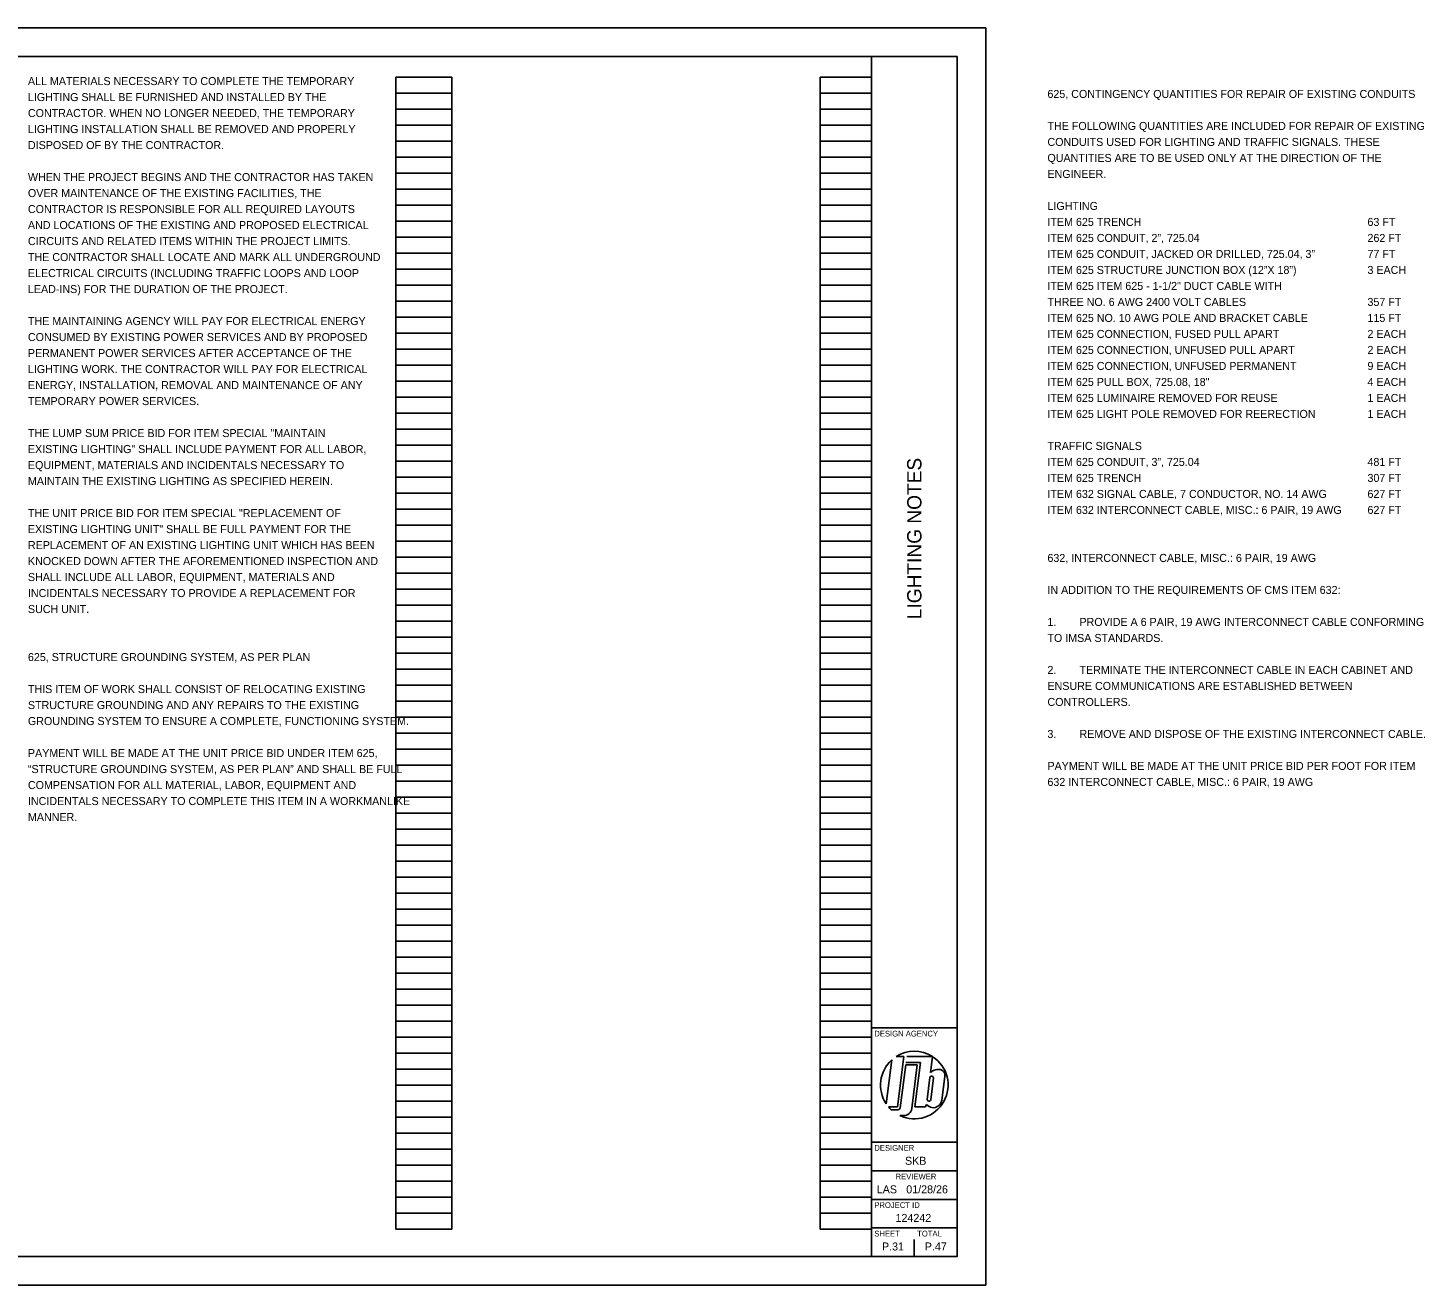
# Model space of a CAD drawing. Extents: x -7.6 to 41.7, y 0 to 22.5.
# Drawn here: x 17.24 to 41.69, y 0 to 22 of the extents above; entities that cross this region are included whole.
import ezdxf

# ---------------------------------------------------------------- set-up
doc = ezdxf.new("R2010")
doc.units = 0
for name, color, linetype in [('SH_Border', 7, 'Continuous'), ('SH_Cut_Line', 7, 'Continuous'), ('SH_Data', 7, 'Continuous'), ('SH_Text', 7, 'Continuous')]:
    doc.layers.add(name, color=color, linetype=linetype)

msp = doc.modelspace()

# ---------------------------------------------------------------- linework, layer by layer
at = {"layer": 'SH_Border'}
for p, q in [((32, 0.5), (32, 21.5)), ((32, 4.5), (33.5, 4.5)), ((32, 2.5), (33.5, 2.5)), ((32, 2), (33.5, 2)), ((32, 1.5), (33.5, 1.5)), ((32, 1), (33.5, 1))]:
    msp.add_line(p, q, dxfattribs=at)
msp.add_lwpolyline([(1.5, 21.5), (33.5, 21.5), (33.5, 0.5), (1.5, 0.5)], close=True, dxfattribs=at)
at = {"layer": 'SH_Cut_Line'}
msp.add_lwpolyline([(0, 0), (34, 0), (34, 22), (0, 22)], close=True, dxfattribs=at)
at = {"layer": 'SH_Data'}
for p, q in [((23.68, 0.98), (23.68, 21.14)), ((23.68, 21.14), (24.66, 21.14)), ((24.66, 0.98), (24.66, 21.14)), ((31.1, 0.98), (31.1, 21.14)), ((31.1, 21.14), (32, 21.14)), ((32, 0.98), (32, 21.14)), ((23.68, 20.86), (24.66, 20.86)), ((31.1, 20.86), (32, 20.86)), ((23.68, 20.58), (24.66, 20.58)), ((31.1, 20.58), (32, 20.58)), ((23.68, 20.3), (24.66, 20.3)), ((31.1, 20.3), (32, 20.3)), ((23.68, 20.02), (24.66, 20.02)), ((31.1, 20.02), (32, 20.02)), ((23.68, 19.74), (24.66, 19.74)), ((31.1, 19.74), (32, 19.74)), ((23.68, 19.46), (24.66, 19.46)), ((31.1, 19.46), (32, 19.46)), ((23.68, 19.18), (24.66, 19.18)), ((31.1, 19.18), (32, 19.18)), ((23.68, 18.9), (24.66, 18.9)), ((31.1, 18.9), (32, 18.9)), ((23.68, 18.62), (24.66, 18.62)), ((31.1, 18.62), (32, 18.62)), ((23.68, 18.34), (24.66, 18.34)), ((31.1, 18.34), (32, 18.34)), ((23.68, 18.06), (24.66, 18.06)), ((31.1, 18.06), (32, 18.06)), ((23.68, 17.78), (24.66, 17.78)), ((31.1, 17.78), (32, 17.78)), ((23.68, 17.5), (24.66, 17.5)), ((31.1, 17.5), (32, 17.5)), ((23.68, 17.22), (24.66, 17.22)), ((31.1, 17.22), (32, 17.22)), ((23.68, 16.94), (24.66, 16.94)), ((31.1, 16.94), (32, 16.94)), ((23.68, 16.66), (24.66, 16.66)), ((31.1, 16.66), (32, 16.66)), ((23.68, 16.38), (24.66, 16.38)), ((31.1, 16.38), (32, 16.38)), ((23.68, 16.1), (24.66, 16.1)), ((31.1, 16.1), (32, 16.1)), ((23.68, 15.82), (24.66, 15.82)), ((31.1, 15.82), (32, 15.82)), ((23.68, 15.54), (24.66, 15.54)), ((31.1, 15.54), (32, 15.54)), ((23.68, 15.26), (24.66, 15.26)), ((31.1, 15.26), (32, 15.26)), ((23.68, 14.98), (24.66, 14.98)), ((31.1, 14.98), (32, 14.98)), ((23.68, 14.7), (24.66, 14.7)), ((31.1, 14.7), (32, 14.7)), ((23.68, 14.42), (24.66, 14.42)), ((31.1, 14.42), (32, 14.42)), ((23.68, 14.14), (24.66, 14.14)), ((31.1, 14.14), (32, 14.14)), ((23.68, 13.86), (24.66, 13.86)), ((31.1, 13.86), (32, 13.86)), ((23.68, 13.58), (24.66, 13.58)), ((31.1, 13.58), (32, 13.58)), ((23.68, 13.3), (24.66, 13.3)), ((31.1, 13.3), (32, 13.3)), ((23.68, 13.02), (24.66, 13.02)), ((31.1, 13.02), (32, 13.02)), ((23.68, 12.74), (24.66, 12.74)), ((31.1, 12.74), (32, 12.74)), ((23.68, 12.46), (24.66, 12.46)), ((31.1, 12.46), (32, 12.46)), ((23.68, 12.18), (24.66, 12.18)), ((31.1, 12.18), (32, 12.18)), ((23.68, 11.9), (24.66, 11.9)), ((31.1, 11.9), (32, 11.9)), ((23.68, 11.62), (24.66, 11.62)), ((31.1, 11.62), (32, 11.62)), ((23.68, 11.34), (24.66, 11.34)), ((31.1, 11.34), (32, 11.34)), ((23.68, 11.06), (24.66, 11.06)), ((31.1, 11.06), (32, 11.06)), ((23.68, 10.78), (24.66, 10.78)), ((31.1, 10.78), (32, 10.78)), ((23.68, 10.5), (24.66, 10.5)), ((31.1, 10.5), (32, 10.5)), ((23.68, 10.22), (24.66, 10.22)), ((31.1, 10.22), (32, 10.22)), ((23.68, 9.94), (24.66, 9.94)), ((31.1, 9.94), (32, 9.94)), ((23.68, 9.66), (24.66, 9.66)), ((31.1, 9.66), (32, 9.66)), ((23.68, 9.38), (24.66, 9.38)), ((31.1, 9.38), (32, 9.38)), ((23.68, 9.1), (24.66, 9.1)), ((31.1, 9.1), (32, 9.1)), ((23.68, 8.82), (24.66, 8.82)), ((31.1, 8.82), (32, 8.82)), ((23.68, 8.54), (24.66, 8.54)), ((31.1, 8.54), (32, 8.54)), ((23.68, 8.26), (24.66, 8.26)), ((31.1, 8.26), (32, 8.26)), ((23.68, 7.98), (24.66, 7.98)), ((31.1, 7.98), (32, 7.98)), ((23.68, 7.7), (24.66, 7.7)), ((31.1, 7.7), (32, 7.7)), ((23.68, 7.42), (24.66, 7.42)), ((31.1, 7.42), (32, 7.42)), ((23.68, 7.14), (24.66, 7.14)), ((31.1, 7.14), (32, 7.14)), ((23.68, 6.86), (24.66, 6.86)), ((31.1, 6.86), (32, 6.86)), ((23.68, 6.58), (24.66, 6.58)), ((31.1, 6.58), (32, 6.58)), ((23.68, 6.3), (24.66, 6.3)), ((31.1, 6.3), (32, 6.3)), ((23.68, 6.02), (24.66, 6.02)), ((31.1, 6.02), (32, 6.02)), ((23.68, 5.74), (24.66, 5.74)), ((31.1, 5.74), (32, 5.74)), ((23.68, 5.46), (24.66, 5.46)), ((31.1, 5.46), (32, 5.46)), ((23.68, 5.18), (24.66, 5.18)), ((31.1, 5.18), (32, 5.18)), ((23.68, 4.9), (24.66, 4.9)), ((31.1, 4.9), (32, 4.9)), ((23.68, 4.62), (24.66, 4.62)), ((31.1, 4.62), (32, 4.62)), ((23.68, 4.34), (24.66, 4.34)), ((31.1, 4.34), (32, 4.34)), ((23.68, 4.06), (24.66, 4.06)), ((31.1, 4.06), (32, 4.06)), ((32.356, 3.94), (32.259, 3.171)), ((32.432, 3.998), (32.567, 3.998)), ((32.567, 3.998), (32.456, 3.118)), ((32.617, 4), (33.065, 4)), ((33.07, 3.996), (33.035, 3.72)), ((23.68, 3.78), (24.66, 3.78)), ((31.1, 3.78), (32, 3.78)), ((32.504, 3.104), (32.599, 3.855)), ((32.599, 3.855), (32.801, 3.855)), ((32.856, 3.896), (32.604, 3.896)), ((32.801, 3.855), (32.704, 3.089)), ((32.758, 3.118), (32.856, 3.896)), ((23.68, 3.5), (24.66, 3.5)), ((31.1, 3.5), (32, 3.5)), ((32.75, 3.5), (32.75, 3.5)), ((33.024, 3.631), (32.976, 3.25)), ((33.036, 3.243), (33.084, 3.624)), ((33.283, 3.648), (33.231, 3.237)), ((23.68, 3.22), (24.66, 3.22)), ((31.1, 3.22), (32, 3.22)), ((23.68, 2.94), (24.66, 2.94)), ((31.1, 2.94), (32, 2.94)), ((32.456, 3.118), (32.299, 3.118)), ((32.347, 3.068), (32.462, 3.068)), ((32.564, 2.966), (32.498, 2.966)), ((32.947, 3.118), (32.758, 3.118)), ((32.964, 3.161), (32.947, 3.118)), ((23.68, 2.66), (24.66, 2.66)), ((31.1, 2.66), (32, 2.66)), ((23.68, 2.38), (24.66, 2.38)), ((31.1, 2.38), (32, 2.38)), ((23.68, 2.1), (24.66, 2.1)), ((31.1, 2.1), (32, 2.1)), ((23.68, 1.82), (24.66, 1.82)), ((31.1, 1.82), (32, 1.82)), ((23.68, 1.54), (24.66, 1.54)), ((31.1, 1.54), (32, 1.54)), ((23.68, 1.26), (24.66, 1.26)), ((31.1, 1.26), (32, 1.26)), ((23.68, 0.98), (24.66, 0.98)), ((31.1, 0.98), (32, 0.98)), ((32.75, 0.5), (32.75, 0.8)), ((32.375, 0.675), (32.375, 0.675))]:
    msp.add_line(p, q, dxfattribs=at)
for centre, radius, start, end in [((32.75, 3.5), 0.591, 131.8253, 213.7822), ((32.75, 3.5), 0.591, 57.726, 122.5688), ((32.75, 3.5), 0.591, 244.7646, 57.1575), ((33.17, 3.586), 0.19, 105.9444, 135.0487), ((33.164, 3.6), 0.175, 66.6782, 105.4185), ((33.177, 3.669), 0.108, 349.2072, 58.7163), ((33.054, 3.628), 0.0301, 352.3298, 173.2777), ((33.081, 3.255), 0.151, 218.6264, 353.0883), ((33.006, 3.246), 0.0301, 172.3335, 353.274), ((32.75, 3.5), 0.591, 220.2786, 227.0158), ((32.462, 3.109), 0.0417, 270, 352.8038), ((32.564, 3.106), 0.141, 270, 352.8038)]:
    msp.add_arc(centre, radius, start, end, dxfattribs=at)

# ---------------------------------------------------------------- texts
msp.add_text('LIGHTING NOTES', height=0.25, rotation=90, dxfattribs=at).set_placement((32.875, 11.653))
for s, height, p in [('DESIGN AGENCY', 0.1, (32.05, 4.35)), ('DESIGNER', 0.1, (32.05, 2.35)), ('SKB', 0.14, (32.587, 2.105)), ('LAS', 0.14, (32.093, 1.605)), ('REVIEWER', 0.1, (32.422, 1.85)), ('01/28/26', 0.14, (32.609, 1.605)), ('PROJECT ID', 0.1, (32.05, 1.35)), ('124242', 0.14, (32.421, 1.105)), ('SHEET', 0.1, (32.05, 0.85)), ('P.31', 0.14, (32.184, 0.605)), ('TOTAL', 0.1, (32.8, 0.85)), ('P.47', 0.14, (32.933, 0.605))]:
    msp.add_text(s, height=height, dxfattribs=at).set_placement(p)
at = {"layer": 'SH_Text'}
for s, p in [('ALL MATERIALS NECESSARY TO COMPLETE THE TEMPORARY', (17.24, 21)), ('LIGHTING SHALL BE FURNISHED AND INSTALLED BY THE', (17.24, 20.72)), ('625, CONTINGENCY QUANTITIES FOR REPAIR OF EXISTING CONDUITS', (35.079, 20.775)), ('CONTRACTOR. WHEN NO LONGER NEEDED, THE TEMPORARY', (17.24, 20.44)), ('LIGHTING INSTALLATION SHALL BE REMOVED AND PROPERLY', (17.24, 20.16)), ('THE FOLLOWING QUANTITIES ARE INCLUDED FOR REPAIR OF EXISTING ', (35.079, 20.215)), ('CONDUITS USED FOR LIGHTING AND TRAFFIC SIGNALS. THESE ', (35.079, 19.935)), ('DISPOSED OF BY THE CONTRACTOR.', (17.24, 19.88)), ('QUANTITIES ARE TO BE USED ONLY AT THE DIRECTION OF THE ', (35.079, 19.655)), ('WHEN THE PROJECT BEGINS AND THE CONTRACTOR HAS TAKEN', (17.24, 19.32)), ('ENGINEER.', (35.079, 19.375)), ('OVER MAINTENANCE OF THE EXISTING FACILITIES, THE', (17.24, 19.04)), ('CONTRACTOR IS RESPONSIBLE FOR ALL REQUIRED LAYOUTS', (17.24, 18.76)), ('LIGHTING', (35.079, 18.815)), ('AND LOCATIONS OF THE EXISTING AND PROPOSED ELECTRICAL', (17.24, 18.48)), ('ITEM 625 TRENCH', (35.079, 18.535)), ('63 FT', (40.679, 18.535)), ('CIRCUITS AND RELATED ITEMS WITHIN THE PROJECT LIMITS.', (17.24, 18.2)), ('ITEM 625 CONDUIT, 2”, 725.04', (35.079, 18.255)), ('262 FT', (40.679, 18.255)), ('ITEM 625 CONDUIT, JACKED OR DRILLED, 725.04, 3” ', (35.079, 17.975)), ('77 FT', (40.679, 17.975)), ('THE CONTRACTOR SHALL LOCATE AND MARK ALL UNDERGROUND', (17.24, 17.92)), ('ELECTRICAL CIRCUITS (INCLUDING TRAFFIC LOOPS AND LOOP', (17.24, 17.64)), ('ITEM 625 STRUCTURE JUNCTION BOX (12”X 18”)', (35.079, 17.695)), ('3 EACH', (40.679, 17.695)), ('LEAD-INS) FOR THE DURATION OF THE PROJECT.', (17.24, 17.36)), ('ITEM 625 ITEM 625 - 1-1/2" DUCT CABLE WITH ', (35.079, 17.415)), ('THREE NO. 6 AWG 2400 VOLT CABLES ', (35.079, 17.135)), ('357 FT', (40.679, 17.135)), ('THE MAINTAINING AGENCY WILL PAY FOR ELECTRICAL ENERGY', (17.24, 16.8)), ('ITEM 625 NO. 10 AWG POLE AND BRACKET CABLE ', (35.079, 16.855)), ('115 FT', (40.679, 16.855)), ('CONSUMED BY EXISTING POWER SERVICES AND BY PROPOSED', (17.24, 16.52)), ('ITEM 625 CONNECTION, FUSED PULL APART', (35.079, 16.575)), ('2 EACH', (40.679, 16.575)), ('PERMANENT POWER SERVICES AFTER ACCEPTANCE OF THE', (17.24, 16.24)), ('ITEM 625 CONNECTION, UNFUSED PULL APART', (35.079, 16.295)), ('2 EACH', (40.679, 16.295)), ('ITEM 625 CONNECTION, UNFUSED PERMANENT', (35.079, 16.015)), ('9 EACH', (40.679, 16.015)), ('LIGHTING WORK. THE CONTRACTOR WILL PAY FOR ELECTRICAL', (17.24, 15.96)), ('ENERGY, INSTALLATION, REMOVAL AND MAINTENANCE OF ANY', (17.24, 15.68)), ('ITEM 625 PULL BOX, 725.08, 18"', (35.079, 15.735)), ('4 EACH', (40.679, 15.735)), ('TEMPORARY POWER SERVICES.', (17.24, 15.4)), ('ITEM 625 LUMINAIRE REMOVED FOR REUSE', (35.079, 15.455)), ('1 EACH', (40.679, 15.455)), ('ITEM 625 LIGHT POLE REMOVED FOR REERECTION ', (35.079, 15.175)), ('1 EACH', (40.679, 15.175)), ('THE LUMP SUM PRICE BID FOR ITEM SPECIAL "MAINTAIN', (17.24, 14.84)), ('EXISTING LIGHTING" SHALL INCLUDE PAYMENT FOR ALL LABOR,', (17.24, 14.56)), ('TRAFFIC SIGNALS', (35.079, 14.615)), ('ITEM 625 CONDUIT, 3”, 725.04', (35.079, 14.335)), ('481 FT', (40.679, 14.335)), ('EQUIPMENT, MATERIALS AND INCIDENTALS NECESSARY TO', (17.24, 14.28)), ('ITEM 625 TRENCH', (35.079, 14.055)), ('307 FT', (40.679, 14.055)), ('MAINTAIN THE EXISTING LIGHTING AS SPECIFIED HEREIN.', (17.24, 14)), ('ITEM 632 SIGNAL CABLE, 7 CONDUCTOR, NO. 14 AWG', (35.079, 13.775)), ('627 FT', (40.679, 13.775)), ('THE UNIT PRICE BID FOR ITEM SPECIAL "REPLACEMENT OF', (17.24, 13.44)), ('ITEM 632 INTERCONNECT CABLE, MISC.: 6 PAIR, 19 AWG', (35.079, 13.495)), ('627 FT', (40.679, 13.495)), ('EXISTING LIGHTING UNIT" SHALL BE FULL PAYMENT FOR THE', (17.24, 13.16)), ('REPLACEMENT OF AN EXISTING LIGHTING UNIT WHICH HAS BEEN', (17.24, 12.88)), ('KNOCKED DOWN AFTER THE AFOREMENTIONED INSPECTION AND', (17.24, 12.6)), ('632, INTERCONNECT CABLE, MISC.: 6 PAIR, 19 AWG', (35.079, 12.655)), ('SHALL INCLUDE ALL LABOR, EQUIPMENT, MATERIALS AND', (17.24, 12.32)), ('IN ADDITION TO THE REQUIREMENTS OF CMS ITEM 632:', (35.079, 12.095)), ('INCIDENTALS NECESSARY TO PROVIDE A REPLACEMENT FOR', (17.24, 12.04)), ('SUCH UNIT.', (17.24, 11.76)), ('1.', (35.079, 11.535)), ('PROVIDE A 6 PAIR, 19 AWG INTERCONNECT CABLE CONFORMING ', (35.639, 11.535)), ('TO IMSA STANDARDS.', (35.079, 11.255)), ('625, STRUCTURE GROUNDING SYSTEM, AS PER PLAN', (17.24, 10.92)), ('2.', (35.079, 10.695)), ('TERMINATE THE INTERCONNECT CABLE IN EACH CABINET AND ', (35.639, 10.695)), ('ENSURE COMMUNICATIONS ARE ESTABLISHED BETWEEN ', (35.079, 10.415)), ('THIS ITEM OF WORK SHALL CONSIST OF RELOCATING EXISTING ', (17.24, 10.36)), ('CONTROLLERS.', (35.079, 10.135)), ('STRUCTURE GROUNDING AND ANY REPAIRS TO THE EXISTING ', (17.24, 10.08)), ('GROUNDING SYSTEM TO ENSURE A COMPLETE, FUNCTIONING SYSTEM.', (17.24, 9.8)), ('3.', (35.079, 9.575)), ('REMOVE AND DISPOSE OF THE EXISTING INTERCONNECT CABLE.', (35.639, 9.575)), ('PAYMENT WILL BE MADE AT THE UNIT PRICE BID UNDER ITEM 625, ', (17.24, 9.24)), ('“STRUCTURE GROUNDING SYSTEM, AS PER PLAN” AND SHALL BE FULL ', (17.24, 8.96)), ('PAYMENT WILL BE MADE AT THE UNIT PRICE BID PER FOOT FOR ITEM ', (35.079, 9.015)), ('COMPENSATION FOR ALL MATERIAL, LABOR, EQUIPMENT AND ', (17.24, 8.68)), ('632 INTERCONNECT CABLE, MISC.: 6 PAIR, 19 AWG', (35.079, 8.735)), ('INCIDENTALS NECESSARY TO COMPLETE THIS ITEM IN A WORKMANLIKE ', (17.24, 8.4)), ('MANNER.', (17.24, 8.12))]:
    msp.add_text(s, height=0.14, dxfattribs=at).set_placement(p)

doc.saveas('drawing.dxf')
